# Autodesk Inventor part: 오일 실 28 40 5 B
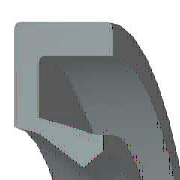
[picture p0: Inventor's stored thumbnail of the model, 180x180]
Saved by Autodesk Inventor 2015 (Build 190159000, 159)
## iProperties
IsCustomPart: 1
Created: 2012-02
Part Number: 오일 실 28 40 5 B
Material: 고무
Description: 오일 실 - 비스프링, 조립 GA
Document SubType Name: Modeling
Standard: JIS B 2402
Designer: mduedu
Standards Organization: JIS
Language: ko-KR
Size Designation: 28 40 5 B
Categories: <MemberInstance><Categories><Category DisplayName="샤프트 부품" InternalName="7f7aeb1f-a693-4053-b835-cee3144e0d98" Mnemonic="SHFT"><Category DisplayName="실링" Intern
Density: 0.93 g/cm^3
Appearance: Rubber-Black
Author: mduedu
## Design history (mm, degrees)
body "Solid1"
revolve "회전1" stored, may be unused: angle "d27" = 360 deg
fillet "모깎기1" dims "d28" = 0.25 (= 0.05 x b)
sketch "스케치2"
  geometry: L1 (15.971, -3.75)-(16.571, -5); L2 (15.171, -3.438)-(15.971, -3.75); L3 (14, -1.375)-(15.171, -3.438); L4 (14.923, -0.75)-(14, -1.375); L5 (17.6, -4.375)-(14.923, -0.75); L6 (17.6, -0.25)-(17.6, -4.375); L7 (18.8, -0.25)-(17.6, -0.25); L8 (18.8, 0)-(18.8, -0.25); L9 (20, 0)-(18.8, 0); L10 (20, -5)-(20, 0); L11 (16.571, -5)-(20, -5); L12 (0, -9.6)-(0, 1.6) reference; L13 (28, 0)-(14, 0) reference
  constraints: 22 end point, 3 horizontal, 3 vertical
  dimensions: "d2" = 5 distance of L10.start L9.start (= b); "d4" = 1.2 distance of L9.start L8.start (= 0.1 x dd - 0.1 x Diam); "d6" = 0.25 distance of L8.start L7.start (= 0.05 x b); "d8" = 0.92308 horizontal distance of L4.start L3.start (= 0.0769231 x dd - 0.0769231 x Diam); "d10" = 0.625 vertical distance of L5.start L10.start (= 0.125 x b); "d12" = 1.2 distance of L7.start L6.start (= 0.1 x dd - 0.1 x Diam); "d14" = 0.5 vertical distance of L4.start L6.start (= 0.1 x b); "d16" = 3.42857 distance of L1.end L10.start (= 0.285714 x dd - 0.285714 x Diam); "d18" = 0.6 horizontal distance of L1.start L1.end (= 0.05 x dd - 0.05 x Diam); "d20" = 0.625 vertical distance of L4.start L3.start (= 0.125 x b); "d22" = 1.25 vertical distance of L1.start L1.end (= 0.25 x b); "d24" = 0.8 horizontal distance of L2.start L1.start (= 0.0666667 x dd - 0.0666667 x Diam); "d26" = 0.3125 vertical distance of L2.start L1.start (= 0.0625 x b); "d29" = 0 distance between parallel lines of L13 L9; "d30" = 14 distance from line of L3.start L12 (= 0.5 x Diam); "d31" = 20 distance between parallel lines of L12 L10 (= 0.5 x dd)
other parameters: "Diam" = 28 [user parameter; used in 7 equation terms], "b" = 5 [user parameter; used in 8 equation terms], "d1" = 8 (derived), "d3" = 2 (derived), "d5" = 0.4 (derived), "d7" = 1.53846 (derived), "d9" = 1 (derived), "d11" = 2 (derived), "d13" = 0.8 (derived), "d15" = 5.71429 (derived), "d17" = 1 (derived), "d19" = 1 (derived), "d21" = 2 (derived), "d23" = 1.33333 (derived), "d25" = 0.5 (derived), "d32" = 0
